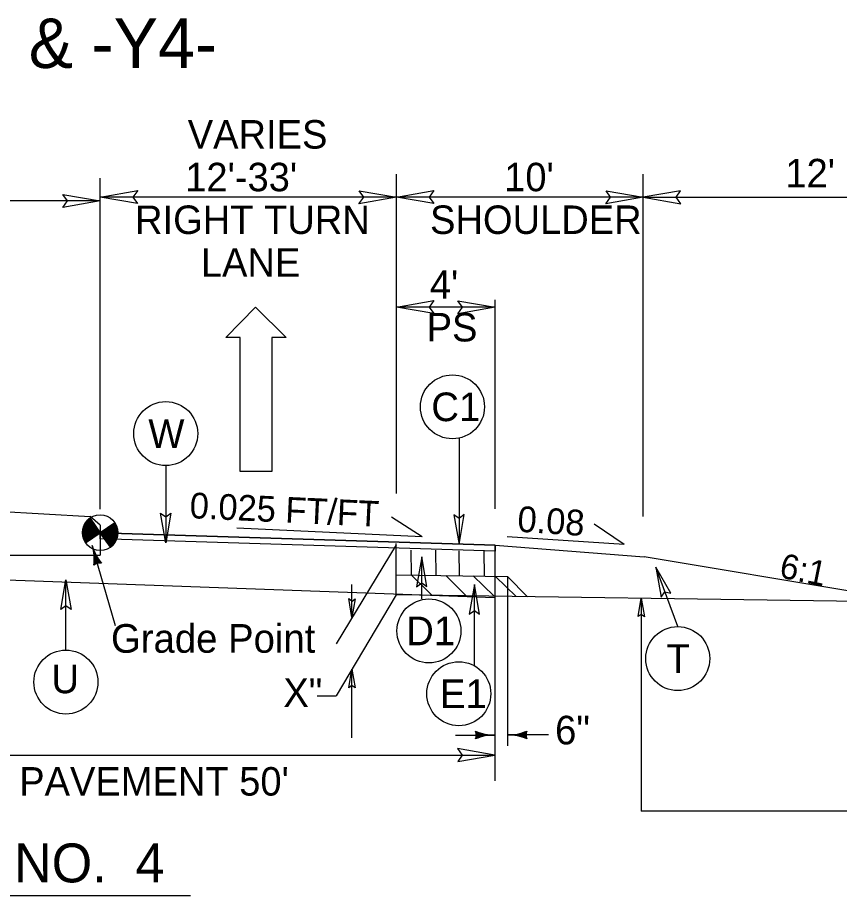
# Model space of a CAD drawing. Extents: x 2176156 to 2177167, y 76401 to 76644.
# Drawn here: x 2177000.61 to 2177033.9, y 76541.23 to 76576.8 of the extents above; entities that cross this region are included whole.
import ezdxf

# ---------------------------------------------------------------- set-up
doc = ezdxf.new("R2010")
doc.units = 0
for name, color, linetype in [('Exist Building', 7, 'Continuous'), ('Exist Building Metal Canopy', 7, 'Continuous'), ('Exist Roads Change in Surface', 7, 'Continuous'), ('Exist Roads Curbs', 7, 'Continuous'), ('Exist Roads EOP Other', 7, 'Continuous'), ('Exist Roads Soil', 7, 'Continuous'), ('Exist Structure Minor Culvert Topo', 7, 'Continuous'), ('Exist Structure Minor Drop Inlet', 7, 'Continuous'), ('Exist Utilities Other Pole CELL', 7, 'Continuous'), ('Exist Vegetation Woods Line', 7, 'Continuous'), ('Model Boundary Lines Text', 7, 'Continuous'), ('Old_Level_1', 7, 'Continuous'), ('Old_Level_3', 7, 'Continuous'), ('Prop North Arrow NAD83 for Plan Sheets CELL', 7, 'Continuous'), ('Sheet Plan CELL', 7, 'Continuous')]:
    doc.layers.add(name, color=color, linetype=linetype)

msp = doc.modelspace()

# ---------------------------------------------------------------- linework, layer by layer
at = {"layer": 'Exist Building'}
for p, q in [((2177015.947, 76553.415), (2177015.947, 76555.488)), ((2177037.063, 76553.101), (2177015.947, 76553.415))]:
    msp.add_line(p, q, dxfattribs=at)
at = {"layer": 'Exist Roads Change in Surface'}
for p, q in [((2177003.548, 76556.519), (2177003.96, 76555.927)), ((2177003.96, 76555.927), (2177004.551, 76556.339)), ((2177003.367, 76555.517), (2177003.96, 76555.927)), ((2177003.96, 76555.927), (2177003.367, 76555.517)), ((2177004.371, 76555.336), (2177003.96, 76555.927))]:
    msp.add_line(p, q, dxfattribs=at)
for points in [[(2177003.599, 76556.445), (2177003.313, 76556.246)], [(2177003.591, 76556.457), (2177003.327, 76556.273)], [(2177003.583, 76556.469), (2177003.343, 76556.303)], [(2177003.574, 76556.481), (2177003.363, 76556.334)], [(2177003.566, 76556.493), (2177003.39, 76556.37)], [(2177003.558, 76556.505), (2177003.424, 76556.411)], [(2177003.55, 76556.516), (2177003.485, 76556.471)], [(2177003.714, 76556.28), (2177003.239, 76555.948)], [(2177003.723, 76556.268), (2177003.239, 76555.931)], [(2177003.731, 76556.256), (2177003.239, 76555.914)], [(2177003.698, 76556.303), (2177003.24, 76555.985)], [(2177003.706, 76556.292), (2177003.24, 76555.967)], [(2177003.739, 76556.244), (2177003.24, 76555.897)], [(2177003.747, 76556.232), (2177003.24, 76555.879)], [(2177003.756, 76556.221), (2177003.242, 76555.863)], [(2177003.69, 76556.315), (2177003.243, 76556.004)], [(2177003.764, 76556.209), (2177003.243, 76555.846)], [(2177003.682, 76556.327), (2177003.245, 76556.023)], [(2177003.772, 76556.197), (2177003.245, 76555.83)], [(2177003.673, 76556.339), (2177003.247, 76556.042)], [(2177003.78, 76556.185), (2177003.248, 76555.814)], [(2177003.665, 76556.351), (2177003.251, 76556.063)], [(2177003.789, 76556.173), (2177003.251, 76555.799)], [(2177003.797, 76556.161), (2177003.254, 76555.783)], [(2177003.657, 76556.363), (2177003.256, 76556.083)], [(2177003.805, 76556.15), (2177003.257, 76555.768)], [(2177003.813, 76556.138), (2177003.26, 76555.753)], [(2177003.649, 76556.374), (2177003.261, 76556.104)], [(2177003.821, 76556.126), (2177003.264, 76555.738)], [(2177003.64, 76556.386), (2177003.267, 76556.126)], [(2177003.83, 76556.114), (2177003.268, 76555.723)], [(2177003.632, 76556.398), (2177003.273, 76556.148)], [(2177003.838, 76556.102), (2177003.273, 76555.709)], [(2177003.846, 76556.09), (2177003.278, 76555.695)], [(2177003.624, 76556.41), (2177003.281, 76556.171)], [(2177003.616, 76556.422), (2177003.29, 76556.195)], [(2177003.607, 76556.434), (2177003.3, 76556.219)], [(2177004.555, 76556.334), (2177004.555, 76556.334), (2177003.963, 76555.922)], [(2177004.563, 76556.322), (2177003.972, 76555.91)], [(2177004.57, 76556.309), (2177003.98, 76555.898)], [(2177004.578, 76556.297), (2177003.988, 76555.887)], [(2177004.585, 76556.285), (2177003.996, 76555.875)], [(2177004.592, 76556.272), (2177004.004, 76555.863)], [(2177004.599, 76556.259), (2177004.013, 76555.851)], [(2177004.606, 76556.246), (2177004.021, 76555.839)], [(2177004.613, 76556.234), (2177004.029, 76555.827)], [(2177004.619, 76556.22), (2177004.037, 76555.816)], [(2177004.624, 76556.206), (2177004.046, 76555.804)], [(2177004.63, 76556.193), (2177004.054, 76555.792)], [(2177004.635, 76556.179), (2177004.062, 76555.78)], [(2177004.64, 76556.164), (2177004.07, 76555.768)], [(2177004.645, 76556.151), (2177004.079, 76555.756)], [(2177004.65, 76556.136), (2177004.087, 76555.745)], [(2177004.654, 76556.122), (2177004.095, 76555.733)], [(2177004.658, 76556.107), (2177004.103, 76555.721)], [(2177004.661, 76556.092), (2177004.112, 76555.709)], [(2177003.854, 76556.079), (2177003.283, 76555.681)], [(2177003.863, 76556.067), (2177003.288, 76555.667)], [(2177003.871, 76556.055), (2177003.294, 76555.653)], [(2177003.879, 76556.043), (2177003.299, 76555.639)], [(2177003.887, 76556.031), (2177003.305, 76555.626)], [(2177003.896, 76556.019), (2177003.312, 76555.613)], [(2177003.904, 76556.008), (2177003.317, 76555.599)], [(2177003.912, 76555.996), (2177003.324, 76555.587)], [(2177003.92, 76555.984), (2177003.331, 76555.574)], [(2177003.929, 76555.972), (2177003.338, 76555.561)], [(2177003.937, 76555.96), (2177003.346, 76555.549)], [(2177003.945, 76555.948), (2177003.353, 76555.537)], [(2177003.953, 76555.937), (2177003.362, 76555.525), (2177003.362, 76555.525)], [(2177004.664, 76556.076), (2177004.12, 76555.697)], [(2177004.667, 76556.061), (2177004.128, 76555.685)], [(2177004.67, 76556.045), (2177004.136, 76555.674)], [(2177004.673, 76556.03), (2177004.145, 76555.662)], [(2177004.675, 76556.013), (2177004.153, 76555.65)], [(2177004.676, 76555.997), (2177004.161, 76555.638)], [(2177004.678, 76555.98), (2177004.169, 76555.626)], [(2177004.68, 76555.964), (2177004.177, 76555.614)], [(2177004.68, 76555.947), (2177004.186, 76555.603)], [(2177004.68, 76555.929), (2177004.194, 76555.591)], [(2177004.679, 76555.911), (2177004.202, 76555.579)], [(2177004.68, 76555.894), (2177004.21, 76555.567)], [(2177004.679, 76555.875), (2177004.219, 76555.555)], [(2177004.677, 76555.856), (2177004.227, 76555.543)], [(2177004.674, 76555.837), (2177004.235, 76555.532)], [(2177004.672, 76555.818), (2177004.243, 76555.52)], [(2177004.668, 76555.798), (2177004.252, 76555.508)], [(2177004.665, 76555.778), (2177004.26, 76555.496)], [(2177004.66, 76555.757), (2177004.268, 76555.484)], [(2177004.654, 76555.735), (2177004.276, 76555.472)], [(2177004.647, 76555.713), (2177004.285, 76555.461)], [(2177004.64, 76555.69), (2177004.293, 76555.449)], [(2177004.631, 76555.667), (2177004.301, 76555.437)], [(2177004.621, 76555.642), (2177004.309, 76555.425)], [(2177004.609, 76555.616), (2177004.317, 76555.413)], [(2177004.597, 76555.59), (2177004.326, 76555.401)], [(2177004.58, 76555.561), (2177004.334, 76555.39)], [(2177004.56, 76555.53), (2177004.342, 76555.378)], [(2177004.536, 76555.495), (2177004.35, 76555.366)], [(2177004.503, 76555.455), (2177004.359, 76555.354)], [(2177004.451, 76555.401), (2177004.367, 76555.342)]]:
    msp.add_lwpolyline(points, dxfattribs=at)
msp.add_circle((2177003.959, 76555.928), 0.721, dxfattribs=at)
for start, end in [(124.8249, 214.8249), (304.8249, 34.8249)]:
    msp.add_arc((2177003.959, 76555.928), 0.721, start, end, dxfattribs=at)
at = {"layer": 'Exist Roads Curbs'}
msp.add_lwpolyline([(2177003.961, 76555.927), (2177003.96, 76555.927), (2177019.96, 76555.428), (2177019.96, 76555.178), (2177003.96, 76555.677), (2177003.96, 76555.677)], close=True, dxfattribs=at)
at = {"layer": 'Exist Roads EOP Other'}
msp.add_line((2177019.96, 76555.428), (2177025.995, 76554.945), dxfattribs=at)
at = {"layer": 'Exist Roads Soil'}
for p, q in [((2176993.894, 76557.141), (2177003.554, 76556.588)), ((2177003.96, 76556.237), (2177003.554, 76556.588)), ((2177003.96, 76556.237), (2177003.96, 76555.024)), ((2177019.96, 76555.428), (2177003.96, 76555.927)), ((2177019.947, 76555.428), (2177019.948, 76554.162)), ((2176983.96, 76555.024), (2177003.96, 76555.024)), ((2177053.947, 76550.287), (2177025.995, 76554.945)), ((2177015.947, 76554.221), (2177020.452, 76554.154)), ((2177020.452, 76554.154), (2177021.275, 76553.336))]:
    msp.add_line(p, q, dxfattribs=at)
at = {"layer": 'Exist Structure Minor Drop Inlet'}
for p, q in [((2177009.049, 76563.842), (2177010.251, 76565.064)), ((2177010.251, 76565.064), (2177011.493, 76563.842)), ((2177009.631, 76563.842), (2177009.049, 76563.842)), ((2177009.631, 76558.41), (2177009.631, 76563.842)), ((2177011.493, 76563.842), (2177010.911, 76563.842)), ((2177010.911, 76563.842), (2177010.911, 76558.41)), ((2177010.911, 76558.41), (2177009.631, 76558.41))]:
    msp.add_line(p, q, dxfattribs=at)
at = {"layer": 'Exist Utilities Other Pole CELL'}
for p, q in [((2177016.996, 76555.759), (2177015.756, 76556.554)), ((2177016.996, 76555.759), (2177009.498, 76556.108)), ((2177025.187, 76555.449), (2177023.963, 76556.268)), ((2177025.187, 76555.449), (2177020.441, 76555.763))]:
    msp.add_line(p, q, dxfattribs=at)
at = {"layer": 'Model Boundary Lines Text'}
for p, q in [((2177016.573, 76554.215), (2177016.559, 76555.226)), ((2177017.571, 76554.191), (2177017.556, 76555.216)), ((2177018.511, 76554.183), (2177018.497, 76555.197)), ((2177019.529, 76554.17), (2177019.515, 76555.186)), ((2177017.383, 76553.411), (2177016.547, 76554.23)), ((2177018.791, 76553.37), (2177017.955, 76554.189)), ((2177019.91, 76553.367), (2177019.074, 76554.185)), ((2177020.803, 76553.348), (2177019.977, 76554.158)), ((2176980.299, 76541.231), (2177007.62, 76541.231))]:
    msp.add_line(p, q, dxfattribs=at)
at = {"layer": 'Old_Level_1'}
for points in [[(2177002.45, 76569.63), (2177003.96, 76569.37), (2177002.442, 76569.101), (2177002.635, 76569.37)], [(2177005.469, 76569.266), (2177003.96, 76569.526), (2177005.478, 76569.794), (2177005.285, 76569.526)], [(2177014.45, 76569.786), (2177015.96, 76569.526), (2177014.442, 76569.257), (2177014.635, 76569.526)], [(2177017.469, 76569.266), (2177015.96, 76569.526), (2177017.478, 76569.794), (2177017.285, 76569.526)], [(2177024.45, 76569.786), (2177025.96, 76569.526), (2177024.442, 76569.257), (2177024.635, 76569.526)], [(2177027.469, 76569.786), (2177025.96, 76569.526), (2177027.478, 76569.257), (2177027.285, 76569.526)], [(2177017.469, 76564.805), (2177015.96, 76565.065), (2177017.478, 76565.334), (2177017.285, 76565.065)], [(2177018.45, 76565.325), (2177019.96, 76565.065), (2177018.442, 76564.797), (2177018.635, 76565.065)], [(2177014.291, 76553.252), (2177014.159, 76552.498), (2177014.027, 76553.257), (2177014.161, 76553.16)], [(2177025.75, 76552.527), (2177025.88, 76553.282), (2177026.014, 76552.523), (2177025.88, 76552.619)], [(2177014.026, 76549.642), (2177014.158, 76550.396), (2177014.29, 76549.637), (2177014.157, 76549.734)], [(2177018.443, 76546.657), (2177019.952, 76546.917), (2177018.434, 76547.186), (2177018.627, 76546.917)]]:
    msp.add_lwpolyline(points, close=True, dxfattribs=at)
at = {"layer": 'Old_Level_3'}
for p, q in [((2177015.96, 76557.514), (2177015.96, 76570.453)), ((2177025.96, 76556.586), (2177025.96, 76570.453)), ((2177003.96, 76556.877), (2177003.96, 76570.297)), ((2177003.96, 76569.37), (2176983.96, 76569.37)), ((2177015.96, 76569.526), (2177003.96, 76569.526)), ((2177025.96, 76569.526), (2177015.96, 76569.526)), ((2177025.96, 76569.526), (2177037.96, 76569.526)), ((2177019.96, 76556.897), (2177019.96, 76565.36)), ((2177019.96, 76565.065), (2177015.96, 76565.065)), ((2177015.947, 76555.431), (2177013.522, 76551.423)), ((2177014.159, 76552.498), (2177014.159, 76553.826)), ((2177015.947, 76553.416), (2177013.522, 76549.321)), ((2177025.88, 76553.282), (2177025.88, 76544.647)), ((2177019.952, 76550.776), (2177019.952, 76545.879)), ((2177014.158, 76547.62), (2177014.158, 76550.396)), ((2177012.742, 76549.321), (2177013.522, 76549.321)), ((2176977.96, 76546.917), (2177019.952, 76546.917)), ((2177035.448, 76544.647), (2177025.88, 76544.647))]:
    msp.add_line(p, q, dxfattribs=at)
at = {"layer": 'Prop North Arrow NAD83 for Plan Sheets CELL'}
for p, q in [((2177018.495, 76559.759), (2177018.495, 76555.456)), ((2177006.616, 76558.648), (2177006.616, 76555.515)), ((2177004.581, 76552.152), (2177003.637, 76555.41)), ((2177016.985, 76553.245), (2177016.985, 76554.945)), ((2177027.355, 76552.124), (2177026.466, 76554.526)), ((2177002.569, 76551.174), (2177002.569, 76554.016)), ((2177019.952, 76554.162), (2177019.952, 76546.793)), ((2177020.452, 76554.149), (2177020.452, 76547.298)), ((2177019.116, 76550.537), (2177019.116, 76553.833)), ((2177018.352, 76547.73), (2177019.952, 76547.73)), ((2177022.119, 76547.733), (2177020.452, 76547.733))]:
    msp.add_line(p, q, dxfattribs=at)
for points in [[(2177006.823, 76556.715), (2177006.616, 76555.515), (2177006.403, 76556.722), (2177006.616, 76556.569)], [(2177018.288, 76556.656), (2177018.495, 76555.456), (2177018.708, 76556.663), (2177018.495, 76556.51)], [(2177017.192, 76553.745), (2177016.985, 76554.945), (2177016.772, 76553.738), (2177016.985, 76553.891)], [(2177027.076, 76553.472), (2177026.466, 76554.526), (2177026.684, 76553.32), (2177026.831, 76553.538)], [(2177002.362, 76552.816), (2177002.569, 76554.016), (2177002.782, 76552.81), (2177002.569, 76552.963)], [(2177019.323, 76552.633), (2177019.116, 76553.833), (2177018.903, 76552.627), (2177019.116, 76552.78)]]:
    msp.add_lwpolyline(points, close=True, dxfattribs=at)
for centre in [(2177018.229, 76561.028), (2177006.616, 76559.944), (2177017.276, 76551.949), (2177027.355, 76550.828), (2177002.569, 76549.878), (2177018.487, 76549.404)]:
    msp.add_circle(centre, 1.296, dxfattribs=at)
for centre, radius, start, end in [((2177005.483, 76555.919), 1.915, 195.408, 219.6854), ((2177001.804, 76554.852), 1.915, 352.6547, 16.9321), ((2177005.483, 76555.919), 1.942, 205.7065, 218.9809), ((2177001.804, 76554.852), 1.942, 353.3593, 6.6337), ((2177003.973, 76554.249), 0.448, 85.4042, 126.9359), ((2177001.804, 76554.852), 1.969, 353.9396, 2.7814), ((2177005.483, 76555.919), 1.969, 209.5588, 218.4006), ((2177001.804, 76554.852), 1.995, 354.4201, 359.873), ((2177005.483, 76555.919), 1.995, 212.4671, 217.9201), ((2177001.804, 76554.852), 2.022, 354.8171, 357.4612), ((2177005.483, 76555.919), 2.022, 214.8789, 217.523), ((2177018.743, 76547.73), 0.448, 339.2339, 20.7656), ((2177019.927, 76549.645), 1.915, 246.4844, 270.7618), ((2177019.927, 76545.815), 1.915, 89.2377, 113.5151), ((2177019.927, 76549.645), 1.942, 247.1889, 260.4633), ((2177019.927, 76545.815), 1.942, 99.5361, 112.8105), ((2177019.927, 76549.645), 1.969, 247.7692, 256.611), ((2177019.927, 76545.815), 1.969, 103.3884, 112.2302), ((2177019.927, 76549.645), 1.995, 248.2497, 253.7027), ((2177019.927, 76545.815), 1.995, 106.2968, 111.7497), ((2177019.927, 76549.645), 2.022, 248.6468, 251.2909), ((2177019.927, 76545.815), 2.022, 108.7086, 111.3527), ((2177020.477, 76549.648), 1.915, 269.2378, 293.5152), ((2177020.477, 76545.818), 1.915, 66.4845, 90.7619), ((2177020.477, 76549.648), 1.942, 279.5362, 292.8107), ((2177020.477, 76545.818), 1.942, 67.189, 80.4635), ((2177020.477, 76549.648), 1.969, 283.3885, 292.2304), ((2177020.477, 76545.818), 1.969, 67.7693, 76.6112), ((2177020.477, 76549.648), 1.995, 286.2969, 291.7498), ((2177020.477, 76545.818), 1.995, 68.2499, 73.7028), ((2177020.477, 76549.648), 2.022, 288.7087, 291.3528), ((2177020.477, 76545.818), 2.022, 68.6469, 71.291), ((2177021.661, 76547.733), 0.448, 159.234, 200.7657)]:
    msp.add_arc(centre, radius, start, end, dxfattribs=at)
at = {"layer": 'Sheet Plan CELL'}
msp.add_line((2177019.949, 76553.295), (2176993.96, 76554.236), dxfattribs=at)

# ---------------------------------------------------------------- texts
at = {"layer": 'Exist Building Metal Canopy'}
msp.add_text('TYPICAL SECTION NO.  4', height=1.5766, rotation=0, dxfattribs=at).set_placement((2176981.144, 76541.76))
at = {"layer": 'Exist Roads Curbs'}
msp.add_text('6:1', height=1.0064, rotation=348.5135, dxfattribs=at).set_placement((2177031.429, 76554.122))
at = {"layer": 'Exist Structure Minor Culvert Topo'}
for s, height, p in [('VARIES ', 1.1533, (2177007.506, 76571.492)), ("12' ", 1.1533, (2177031.716, 76569.921)), ("12'-33' ", 1.1533, (2177007.404, 76569.762)), ("10' ", 1.1533, (2177020.324, 76569.763)), ('RIGHT TURN ', 1.15334, (2177005.371, 76568.032)), ('SHOULDER', 1.1533, (2177017.322, 76568.033)), ('LANE', 1.1533, (2177008.037, 76566.301)), ("4' ", 1.1533, (2177017.312, 76565.407)), ('PS', 1.1533, (2177017.183, 76563.677)), ("EXIST. PAVEMENT 50'", 1.15334, (2176995.365, 76545.277))]:
    msp.add_text(s, height=height, dxfattribs=at).set_placement(p)
at = {"layer": 'Exist Utilities Other Pole CELL'}
for s, height, rotation, p in [('0.025 FT/FT', 1.04295, 357.3324, (2177007.567, 76556.52)), ('0.08', 1.0429, 356.2199, (2177020.837, 76555.973))]:
    msp.add_text(s, height=height, rotation=rotation, dxfattribs=at).set_placement(p)
at = {"layer": 'Exist Vegetation Woods Line'}
msp.add_text('C -Y1- & -Y4-', height=2.01314, dxfattribs=at).set_placement((2176992.539, 76574.757))
at = {"layer": 'Prop North Arrow NAD83 for Plan Sheets CELL'}
for s, rotation, p in [('C1', 359.9997, (2177017.373, 76560.448)), ('W', 0.0003, (2177005.909, 76559.364)), ('D1', 359.9997, (2177016.355, 76551.369)), ('Grade Point', 0.0002, (2177004.397, 76551.065)), ('T', 359.9997, (2177026.898, 76550.248)), ('U', 0.0003, (2177001.983, 76549.424)), ('E1', 359.9997, (2177017.724, 76548.824)), ('6"', 359.9998, (2177022.385, 76547.352))]:
    msp.add_text(s, height=1.16, rotation=rotation, dxfattribs=at).set_placement(p)
msp.add_text('X"', height=1.1533, dxfattribs=at).set_placement((2177011.38, 76548.871))

doc.saveas('drawing.dxf')
